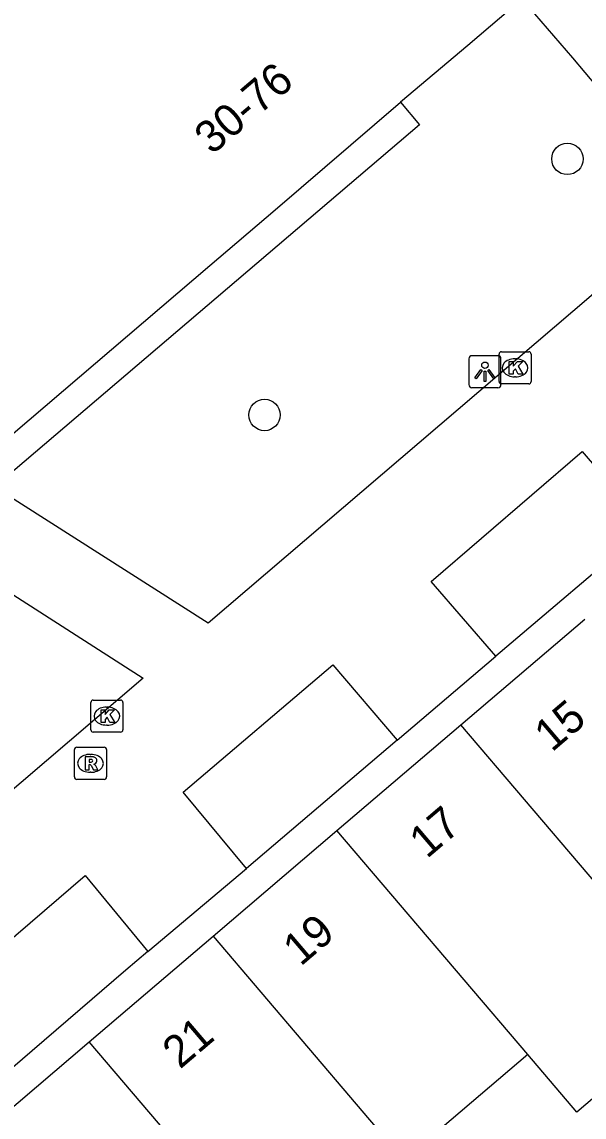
# Model space of a CAD drawing. Extents: x 160379 to 161131, y 383940 to 384849.
# Drawn here: x 160708.69 to 160726.2, y 384636.19 to 384670.33 of the extents above; entities that cross this region are included whole.
import ezdxf

# ---------------------------------------------------------------- set-up
doc = ezdxf.new("R2010")
doc.units = 0
for name, color, linetype in [('IMGEO_Boom', 7, 'Continuous'), ('IMGEO_Groenvoorziening', 7, 'Continuous'), ('IMGEO_Kolk', 7, 'Continuous'), ('IMGEO_Lichtpunt', 7, 'Continuous'), ('IMGEO_Pand', 7, 'Continuous'), ('IMGEO_Pand_nummerreeks', 7, 'Continuous'), ('IMGEO_Rioolput', 7, 'Continuous'), ('IMGEO_Voetgangersgebied_open', 7, 'Continuous')]:
    doc.layers.add(name, color=color, linetype=linetype)

msp = doc.modelspace()

# ---------------------------------------------------------------- linework, layer by layer
at = {"layer": 'IMGEO_Boom'}
for centre in [(160725.683, 384666.054), (160716.247, 384658.073)]:
    msp.add_circle(centre, 0.489, dxfattribs=at)
at = {"layer": 'IMGEO_Groenvoorziening'}
for points in [[(160720.487, 384667.819), (160721.073, 384667.118), (160707.836, 384655.834)], [(160728.177, 384654.568), (160723.454, 384650.553)], [(160720.379, 384647.933), (160715.683, 384643.941)], [(160712.616, 384641.352), (160711.93, 384640.763), (160707.952, 384637.348)]]:
    msp.add_lwpolyline(points, dxfattribs=at)
at = {"layer": 'IMGEO_Kolk'}
for p, q in [((160723.553, 384659.117), (160723.553, 384659.969)), ((160723.628, 384660.043), (160724.48, 384660.043)), ((160724.554, 384659.969), (160724.554, 384659.117)), ((160724.041, 384659.823), (160724.066, 384659.823)), ((160724.48, 384659.043), (160723.628, 384659.043)), ((160724.064, 384659.263), (160724.039, 384659.263)), ((160710.835, 384648.261), (160710.835, 384649.113)), ((160710.91, 384649.187), (160711.762, 384649.187)), ((160711.836, 384649.113), (160711.836, 384648.261)), ((160711.323, 384648.967), (160711.348, 384648.967)), ((160711.346, 384648.407), (160711.321, 384648.407)), ((160711.762, 384648.187), (160710.91, 384648.187))]:
    msp.add_line(p, q, dxfattribs=at)
for points in [[(160723.553, 384659.117), (160723.553, 384659.969)], [(160723.628, 384660.043), (160724.48, 384660.043)], [(160724.554, 384659.969), (160724.554, 384659.117)], [(160723.874, 384659.743), (160723.997, 384659.743), (160723.997, 384659.592), (160724.127, 384659.743), (160724.291, 384659.743), (160724.145, 384659.592), (160724.298, 384659.343), (160724.146, 384659.343), (160724.061, 384659.507), (160723.997, 384659.44), (160723.997, 384659.343), (160723.874, 384659.343), (160723.874, 384659.743)], [(160724.48, 384659.043), (160723.628, 384659.043)], [(160710.835, 384648.261), (160710.835, 384649.113)], [(160710.91, 384649.187), (160711.762, 384649.187)], [(160711.836, 384649.113), (160711.836, 384648.261)], [(160711.156, 384648.887), (160711.279, 384648.887), (160711.279, 384648.736), (160711.409, 384648.887), (160711.573, 384648.887), (160711.427, 384648.736), (160711.58, 384648.487), (160711.428, 384648.487), (160711.343, 384648.651), (160711.279, 384648.584), (160711.279, 384648.487), (160711.156, 384648.487), (160711.156, 384648.887)], [(160711.762, 384648.187), (160710.91, 384648.187)]]:
    msp.add_lwpolyline(points, dxfattribs=at)
for centre, start, end in [((160723.63, 384659.967), 91.552, 178.448), ((160723.63, 384659.967), 91.552, 178.448), ((160724.478, 384659.967), 1.552, 88.448), ((160724.478, 384659.967), 1.552, 88.448), ((160723.63, 384659.119), 181.552, 268.448), ((160723.63, 384659.119), 181.552, 268.448), ((160724.478, 384659.119), 271.552, 358.448), ((160724.478, 384659.119), 271.552, 358.448), ((160710.912, 384649.111), 91.552, 178.448), ((160710.912, 384649.111), 91.552, 178.448), ((160711.76, 384649.111), 1.552, 88.448), ((160711.76, 384649.111), 1.552, 88.448), ((160710.912, 384648.263), 181.552, 268.448), ((160710.912, 384648.263), 181.552, 268.448), ((160711.76, 384648.263), 271.552, 358.448), ((160711.76, 384648.263), 271.552, 358.448)]:
    msp.add_arc(centre, 0.0765, start, end, dxfattribs=at)
for centre, major_axis, ratio, start_param, end_param in [((160724.04, 384659.543), (-0.387, 0.002), 0.722429, 4.712389, 7.853982), ((160724.065, 384659.543), (-0.39, 0.002), 0.717154, 1.570796, 4.712389), ((160711.322, 384648.687), (-0.387, 0.002), 0.722429, 4.712389, 7.853982), ((160711.347, 384648.687), (-0.39, 0.002), 0.717154, 1.570796, 4.712389)]:
    msp.add_ellipse(centre, major_axis=major_axis, ratio=ratio, start_param=start_param, end_param=end_param, dxfattribs=at)
at = {"layer": 'IMGEO_Lichtpunt'}
for p, q in [((160722.615, 384659.826), (160722.615, 384659.019)), ((160722.615, 384659.826), (160722.615, 384659.019)), ((160723.517, 384659.921), (160722.709, 384659.921)), ((160723.517, 384659.921), (160722.709, 384659.921)), ((160723.611, 384659.019), (160723.611, 384659.826)), ((160723.611, 384659.019), (160723.611, 384659.826)), ((160722.709, 384658.925), (160723.517, 384658.925)), ((160722.709, 384658.925), (160723.517, 384658.925))]:
    msp.add_line(p, q, dxfattribs=at)
for points in [[(160722.989, 384659.49), (160723.028, 384659.462), (160722.84, 384659.2), (160722.802, 384659.227), (160722.989, 384659.49)], [(160723.091, 384659.442), (160723.138, 384659.442), (160723.138, 384659.12), (160723.091, 384659.12), (160723.091, 384659.442)], [(160723.201, 384659.462), (160723.239, 384659.489), (160723.426, 384659.227), (160723.387, 384659.199), (160723.201, 384659.462)]]:
    msp.add_lwpolyline(points, dxfattribs=at)
msp.add_circle((160723.114, 384659.624), 0.0994, dxfattribs=at)
for centre, start, end in [((160722.709, 384659.826), 90, 180), ((160722.709, 384659.826), 90, 180), ((160723.517, 384659.826), 0, 90), ((160723.517, 384659.826), 0, 90), ((160722.709, 384659.019), 180, 270), ((160722.709, 384659.019), 180, 270), ((160723.517, 384659.019), 270, 0), ((160723.517, 384659.019), 270, 360)]:
    msp.add_arc(centre, 0.0946, start, end, dxfattribs=at)
at = {"layer": 'IMGEO_Pand'}
for points in [[(160724.276, 384671.043), (160722.578, 384669.588), (160720.487, 384667.819)], [(160689.421, 384668.806), (160707.911, 384657.071), (160714.54, 384662.736), (160716.576, 384664.468), (160720.487, 384667.819)], [(160722.366, 384648.414), (160726.228, 384651.708)], [(160718.504, 384645.12), (160722.366, 384648.414)], [(160729.844, 384639.636), (160728.315, 384641.431), (160722.366, 384648.414)], [(160714.642, 384641.826), (160718.504, 384645.12)], [(160724.452, 384638.139), (160718.504, 384645.12)], [(160710.78, 384638.533), (160714.642, 384641.826)], [(160714.642, 384641.826), (160720.588, 384634.847)], [(160729.844, 384639.636), (160725.98, 384636.345), (160724.452, 384638.139)], [(160706.918, 384635.239), (160710.78, 384638.533)], [(160718.264, 384629.748), (160716.721, 384631.559), (160710.78, 384638.533)], [(160724.452, 384638.139), (160720.588, 384634.847)]]:
    msp.add_lwpolyline(points, dxfattribs=at)
at = {"layer": 'IMGEO_Rioolput'}
for p, q in [((160710.4, 384647.715), (160711.252, 384647.715)), ((160710.325, 384646.789), (160710.325, 384647.641)), ((160710.813, 384647.495), (160710.838, 384647.495)), ((160711.326, 384647.641), (160711.326, 384646.789)), ((160711.252, 384646.715), (160710.4, 384646.715)), ((160710.836, 384646.935), (160710.811, 384646.935))]:
    msp.add_line(p, q, dxfattribs=at)
for points in [[(160710.4, 384647.715), (160711.252, 384647.715)], [(160710.325, 384646.789), (160710.325, 384647.641)], [(160710.914, 384647.413), (160710.662, 384647.415), (160710.662, 384647.015)], [(160710.84, 384647.334), (160710.786, 384647.334), (160710.786, 384647.253)], [(160711.326, 384647.641), (160711.326, 384646.789)], [(160710.662, 384647.015), (160710.786, 384647.015), (160710.786, 384647.177), (160710.797, 384647.177)], [(160710.786, 384647.253), (160710.838, 384647.253)], [(160710.844, 384647.148), (160710.915, 384647.015), (160711.055, 384647.015), (160710.99, 384647.141)], [(160711.252, 384646.715), (160710.4, 384646.715)]]:
    msp.add_lwpolyline(points, dxfattribs=at)
for centre, radius, start, end in [((160710.402, 384647.639), 0.0765, 91.552, 178.448), ((160710.402, 384647.639), 0.0765, 91.552, 178.448), ((160711.25, 384647.639), 0.0765, 1.552, 88.448), ((160711.25, 384647.639), 0.0765, 1.552, 88.448), ((160710.846, 384647.238), 0.0964, 77.0061, 93.1865), ((160710.86, 384647.295), 0.0378, 276.6634, 79.6772), ((160710.913, 384647.303), 0.109, 350.3612, 89.416), ((160710.796, 384647.124), 0.0533, 26.0293, 88.6989), ((160710.822, 384647.442), 0.19, 274.7715, 282.9687), ((160710.911, 384647.303), 0.112, 277.5842, 350.9817), ((160710.895, 384647.088), 0.108, 29.5134, 73.7905), ((160710.402, 384646.791), 0.0765, 181.552, 268.448), ((160710.402, 384646.791), 0.0765, 181.552, 268.448), ((160711.25, 384646.791), 0.0765, 271.552, 358.448), ((160711.25, 384646.791), 0.0765, 271.552, 358.448)]:
    msp.add_arc(centre, radius, start, end, dxfattribs=at)
for centre, major_axis, ratio, start_param, end_param in [((160710.812, 384647.215), (-0.387, 0.002), 0.722429, 4.712389, 7.853982), ((160710.837, 384647.215), (-0.39, 0.002), 0.717154, 1.570796, 4.712389)]:
    msp.add_ellipse(centre, major_axis=major_axis, ratio=ratio, start_param=start_param, end_param=end_param, dxfattribs=at)
at = {"layer": 'IMGEO_Voetgangersgebied_open'}
for points in [[(160707.836, 384655.834), (160714.493, 384651.594), (160734.284, 384668.52), (160732.734, 384670.347), (160728.159, 384666.466), (160725.852, 384669.204), (160724.276, 384671.043)], [(160723.454, 384650.553), (160721.435, 384652.883), (160726.14, 384656.932), (160728.177, 384654.568)], [(160707.002, 384653.367), (160712.463, 384649.871), (160707.15, 384645.327)], [(160720.379, 384647.933), (160723.454, 384650.553)], [(160715.683, 384643.941), (160713.716, 384646.315), (160718.375, 384650.288), (160720.379, 384647.933)], [(160712.616, 384641.352), (160715.683, 384643.941)], [(160707.952, 384637.348), (160705.952, 384639.673), (160710.66, 384643.716), (160712.616, 384641.352)]]:
    msp.add_lwpolyline(points, dxfattribs=at)

# ---------------------------------------------------------------- texts
at = {"layer": 'IMGEO_Pand_nummerreeks'}
for s, rotation, p in [('30-76', 40.3763, (160714.609, 384666.16)), ('15', 40.4565, (160725.197, 384647.543)), ('17', 40.4565, (160721.303, 384644.222)), ('19', 40.4565, (160717.369, 384640.867)), ('21', 40.4565, (160713.612, 384637.663))]:
    msp.add_text(s, height=1, rotation=rotation, dxfattribs=at).set_placement(p)

doc.saveas('drawing.dxf')
